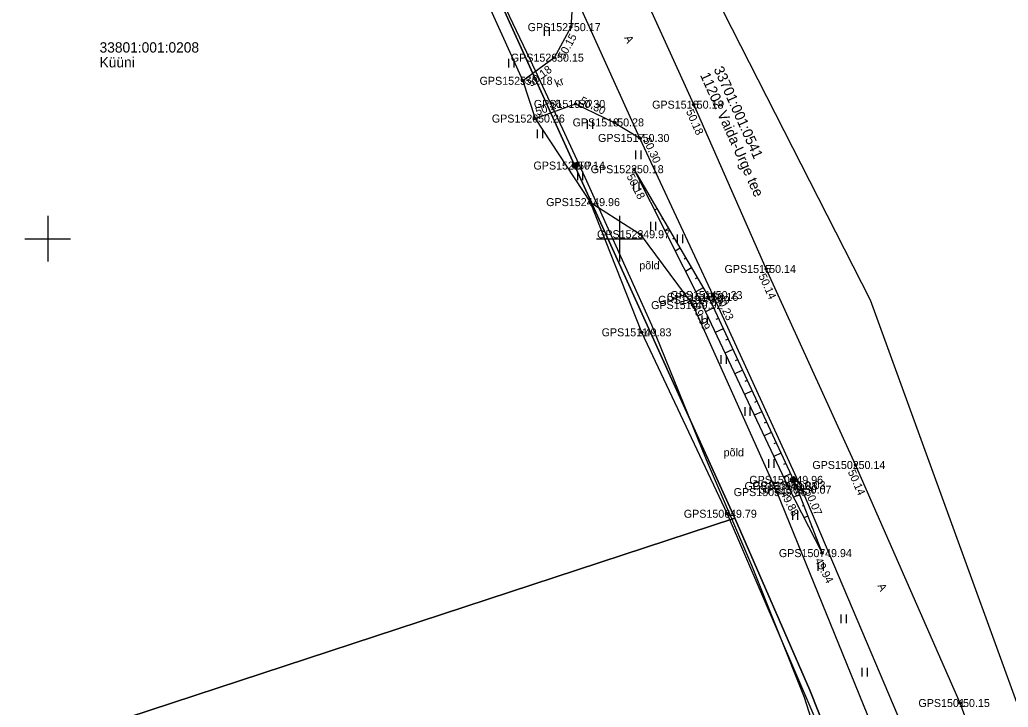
# Model space of a CAD drawing. Extents: x 551623 to 559850, y 6561220 to 6567135.
# Drawn here: x 555097.6 to 555184, y 6565359 to 6565419.1 of the extents above; entities that cross this region are included whole.
import ezdxf

# ---------------------------------------------------------------- set-up
doc = ezdxf.new("R2010")
doc.units = 0
for name, color, linetype in [('HALJASTUS', 7, 'Continuous'), ('KORGUS-EH2000', 7, 'Continuous'), ('KPKAABEL', 7, 'Continuous'), ('MOOTKORG-EH2000', 7, 'Continuous'), ('MOOTMPUNKT', 7, 'Continuous'), ('MOOTNR', 7, 'Continuous'), ('MOOTPIIR', 7, 'Continuous'), ('PIIR', 7, 'Continuous'), ('POST', 7, 'Continuous'), ('RELJEEF', 7, 'Continuous'), ('TEE', 7, 'Continuous'), ('VORK', 7, 'Continuous')]:
    doc.layers.add(name, color=color, linetype=linetype)

msp = doc.modelspace()

# ---------------------------------------------------------------- linework, layer by layer
at = {"layer": 'HALJASTUS'}
for p, q in [((555143.4, 6565418.501), (555143.4, 6565417.739)), ((555143.855, 6565418.501), (555143.855, 6565417.739)), ((555140.305, 6565415.73), (555140.305, 6565414.969)), ((555140.76, 6565415.73), (555140.76, 6565414.969)), ((555147.172, 6565410.363), (555147.172, 6565409.602)), ((555147.627, 6565410.363), (555147.627, 6565409.602)), ((555142.801, 6565409.556), (555142.801, 6565408.795)), ((555143.256, 6565409.556), (555143.256, 6565408.795)), ((555151.41, 6565407.71), (555151.41, 6565406.949)), ((555151.865, 6565407.71), (555151.865, 6565406.949)), ((555146.315, 6565405.877), (555146.315, 6565405.116)), ((555146.77, 6565405.877), (555146.77, 6565405.116)), ((555151.235, 6565404.982), (555151.235, 6565404.221)), ((555151.69, 6565404.982), (555151.69, 6565404.221)), ((555152.696, 6565401.486), (555152.696, 6565400.724)), ((555153.151, 6565401.486), (555153.151, 6565400.724)), ((555155.056, 6565400.377), (555155.056, 6565399.616)), ((555155.511, 6565400.377), (555155.511, 6565399.616)), ((555157.198, 6565393.27), (555157.198, 6565392.509)), ((555157.654, 6565393.27), (555157.654, 6565392.509)), ((555158.86, 6565389.801), (555158.86, 6565389.04)), ((555159.315, 6565389.801), (555159.315, 6565389.04)), ((555160.947, 6565385.258), (555160.947, 6565384.497)), ((555161.402, 6565385.258), (555161.402, 6565384.497)), ((555163.034, 6565380.714), (555163.034, 6565379.953)), ((555163.489, 6565380.714), (555163.489, 6565379.953)), ((555165.121, 6565376.171), (555165.121, 6565375.41)), ((555165.576, 6565376.171), (555165.576, 6565375.41)), ((555167.351, 6565371.697), (555167.351, 6565370.935)), ((555167.806, 6565371.697), (555167.806, 6565370.935)), ((555169.366, 6565367.127), (555169.366, 6565366.366)), ((555169.821, 6565367.127), (555169.821, 6565366.366)), ((555171.205, 6565362.477), (555171.205, 6565361.716)), ((555171.66, 6565362.477), (555171.66, 6565361.716))]:
    msp.add_line(p, q, dxfattribs=at)
msp.add_lwpolyline([(555147.437, 6565403.198), (555151.813, 6565400.39), (555156.402, 6565394.192), (555163.761, 6565377.834), (555172.39, 6565356.6), (555175.608, 6565345.88), (555178.387, 6565334.156), (555180.524, 6565321.581), (555178.521, 6565317.128)], dxfattribs=at)
at = {"layer": 'KORGUS-EH2000'}
for centre in [(555144.275, 6565415.829), (555141.543, 6565413.808), (555146.15, 6565411.784), (555156.491, 6565411.721), (555142.614, 6565410.505), (555151.76, 6565408.809), (555151.259, 6565406.076), (555147.437, 6565403.198), (555151.813, 6565400.39), (555162.823, 6565397.349), (555158.151, 6565395.066), (555157.023, 6565394.648), (555151.936, 6565391.81), (555170.643, 6565380.205), (555164.713, 6565378.366), (555165.412, 6565378.436), (555165.93, 6565378.047), (555159.402, 6565375.941), (555167.716, 6565372.497), (555179.78, 6565359.387)]:
    msp.add_circle(centre, 0.1, dxfattribs=at)
at = {"layer": 'KPKAABEL'}
msp.add_lwpolyline([(555062.108, 6565572.667), (555068.248, 6565560.982), (555073.771, 6565549.852), (555080.106, 6565537.978), (555085.958, 6565527.605), (555092.403, 6565515.607), (555098.402, 6565504.536), (555104.641, 6565492.438), (555110.839, 6565480.82), (555116.697, 6565469.072), (555121.821, 6565458.116), (555126.894, 6565446.731), (555132.737, 6565435.388), (555136.366, 6565427.872), (555142.195, 6565415.637), (555145.001, 6565409.613), (555146.957, 6565405.365), (555152.799, 6565392.474), (555157.576, 6565380.671), (555161.529, 6565371.444), (555166.139, 6565359.889), (555169.783, 6565348.422)], dxfattribs=at)
at = {"layer": 'MOOTMPUNKT'}
for centre in [(555145.745, 6565418.501), (555144.275, 6565415.829), (555141.543, 6565413.808), (555146.15, 6565411.784), (555156.491, 6565411.721), (555142.614, 6565410.505), (555149.538, 6565410.169), (555151.76, 6565408.809), (555146.117, 6565406.394), (555151.259, 6565406.076), (555147.437, 6565403.198), (555151.813, 6565400.39), (555162.823, 6565397.349), (555158.151, 6565395.066), (555156.402, 6565394.192), (555157.023, 6565394.648), (555157.779, 6565394.908), (555151.936, 6565391.81), (555170.643, 6565380.205), (555165.2, 6565378.903), (555163.761, 6565377.834), (555164.713, 6565378.366), (555165.412, 6565378.436), (555165.93, 6565378.047), (555159.402, 6565375.941), (555167.716, 6565372.497), (555179.78, 6565359.387)]:
    msp.add_circle(centre, 0.1, dxfattribs=at)
at = {"layer": 'MOOTPIIR'}
for points in [[(555183.958, 6565348.1), (555179.78, 6565359.387), (555170.643, 6565380.205), (555162.823, 6565397.349), (555156.491, 6565411.721), (555150.933, 6565424.006), (555146.697, 6565433.416), (555136.695, 6565455.531), (555128.269, 6565473.276), (555117.193, 6565494.735), (555104.647, 6565516.948), (555091.543, 6565539.738), (555085.215, 6565551.468), (555079.648, 6565563.241), (555074.002, 6565577.71)], [(555063.202, 6565573.546), (555069.448, 6565559.262), (555074.798, 6565546.065), (555081.393, 6565533.703), (555093.795, 6565510.023), (555105.564, 6565489.366), (555116.679, 6565467.661), (555125.053, 6565451.606), (555137.448, 6565422.907), (555141.543, 6565413.808), (555142.614, 6565410.505), (555147.437, 6565403.198), (555151.936, 6565391.81), (555159.402, 6565375.941), (555168.348, 6565355.185)]]:
    msp.add_lwpolyline(points, dxfattribs=at)
at = {"layer": 'PIIR'}
for points in [[(555524.79, 6565820.16), (555464.46, 6565652.92), (555447.97, 6565611.96), (555353.12, 6565523.87), (555343.14, 6565512.46), (555302.6, 6565539.71), (555242.37, 6565583.94), (555179.42, 6565586.32), (555138.98, 6565580.6), (555121.18, 6565602.26), (555116.17, 6565610.5), (555109.96, 6565624.83), (555093.56, 6565628.47), (555079.04, 6565618.4), (555074.13, 6565607.82), (555075.34, 6565593.24), (555091.74, 6565551.94), (555171.91, 6565394.64), (555191.35, 6565341.19)], [(554759.9, 6565289.12), (554708.97, 6565534.83), (554708.61, 6565545.48), (554711.27, 6565557.85), (554755.81, 6565778.04), (554759.53, 6565776.27), (554842.52, 6565736.67), (555030.24, 6565648.23), (555043.11, 6565640.11), (555053.62, 6565632.14), (555056.61, 6565622.91), (555057.22, 6565600.73), (555060.42, 6565583.26), (555065.78, 6565566.7), (555076.76, 6565542.38), (555113.82, 6565475.68), (554946.63, 6565420.78), (554981.01, 6565316.76), (555160.07, 6565375.54), (555166.64, 6565360.5), (555172.72, 6565345.23)], [(555172.72, 6565345.23), (555166.64, 6565360.5), (555160.07, 6565375.54), (555144.16, 6565410.6), (555124.27, 6565454.45), (555113.82, 6565475.68), (555076.76, 6565542.38), (555065.78, 6565566.7), (555060.42, 6565583.26), (555057.22, 6565600.73), (555056.61, 6565622.91), (555063.43, 6565647.29), (555114.24, 6565634), (555129.77, 6565611.2), (555130.73, 6565621.32), (555138.66, 6565615.26), (555160.12, 6565598.86), (555193.24, 6565604.68)]]:
    msp.add_lwpolyline(points, dxfattribs=at)
msp.add_lwpolyline([(554981.01, 6565316.76), (554946.63, 6565420.78), (555113.82, 6565475.68), (555124.27, 6565454.45), (555144.16, 6565410.6), (555160.07, 6565375.54)], close=True, dxfattribs=at)
at = {"layer": 'POST'}
msp.add_line((555165.022, 6565378.727), (555165.376, 6565379.08), dxfattribs=at)
for centre, radius in [((555146.117, 6565406.394), 0.25), ((555146.117, 6565406.394), 0.225), ((555146.117, 6565406.394), 0.2), ((555146.117, 6565406.394), 0.175), ((555146.117, 6565406.394), 0.15), ((555146.117, 6565406.394), 0.125), ((555146.117, 6565406.394), 0.1), ((555146.117, 6565406.394), 0.075), ((555146.117, 6565406.394), 0.05), ((555146.117, 6565406.394), 0.025), ((555165.2, 6565378.903), 0.25)]:
    msp.add_circle(centre, radius, dxfattribs=at)
for radius, start, end in [(0.225, 224.85406, 45.03563), (0.2, 224.84272, 45.04698), (0.175, 224.82813, 45.06157), (0.15, 224.80867, 45.08103), (0.125, 224.78144, 45.10826), (0.1, 224.74058, 45.14911), (0.075, 224.67249, 45.2172), (0.05, 224.53632, 45.35338), (0.025, 224.12776, 45.76193)]:
    msp.add_arc((555165.2, 6565378.903), radius, start, end, dxfattribs=at)
at = {"layer": 'RELJEEF'}
for p, q in [((555151.764, 6565405.213), (555151.748, 6565405.203)), ((555152.268, 6565404.349), (555152.162, 6565404.287)), ((555152.772, 6565403.485), (555152.724, 6565403.458)), ((555153.276, 6565402.622), (555153.064, 6565402.498)), ((555153.78, 6565401.758), (555153.701, 6565401.712)), ((555154.284, 6565400.895), (555153.966, 6565400.709)), ((555154.788, 6565400.031), (555154.677, 6565399.966)), ((555155.292, 6565399.167), (555154.868, 6565398.92)), ((555155.796, 6565398.304), (555155.653, 6565398.22)), ((555156.301, 6565397.44), (555155.771, 6565397.131)), ((555156.805, 6565396.576), (555156.63, 6565396.474)), ((555157.309, 6565395.713), (555156.673, 6565395.341)), ((555157.807, 6565394.846), (555157.591, 6565394.746)), ((555158.228, 6565393.939), (555157.514, 6565393.608)), ((555158.648, 6565393.031), (555158.436, 6565392.933)), ((555159.069, 6565392.124), (555158.368, 6565391.799)), ((555159.489, 6565391.217), (555159.281, 6565391.12)), ((555159.91, 6565390.31), (555159.222, 6565389.991)), ((555160.33, 6565389.402), (555160.126, 6565389.308)), ((555160.751, 6565388.495), (555160.076, 6565388.183)), ((555161.171, 6565387.588), (555160.971, 6565387.495)), ((555161.592, 6565386.68), (555160.931, 6565386.374)), ((555162.012, 6565385.773), (555161.816, 6565385.682)), ((555162.432, 6565384.866), (555161.785, 6565384.566)), ((555162.853, 6565383.958), (555162.661, 6565383.869)), ((555163.273, 6565383.051), (555162.639, 6565382.757)), ((555163.694, 6565382.144), (555163.505, 6565382.057)), ((555164.114, 6565381.237), (555163.493, 6565380.949)), ((555164.535, 6565380.329), (555164.35, 6565380.244)), ((555164.955, 6565379.422), (555164.347, 6565379.14)), ((555165.376, 6565378.515), (555165.197, 6565378.432)), ((555165.742, 6565377.584), (555165.217, 6565377.381)), ((555166.104, 6565376.652), (555165.975, 6565376.602)), ((555166.466, 6565375.72), (555166.133, 6565375.591)), ((555166.827, 6565374.787), (555166.756, 6565374.76)), ((555167.189, 6565373.855), (555167.049, 6565373.801)), ((555167.55, 6565372.923), (555167.537, 6565372.918))]:
    msp.add_line(p, q, dxfattribs=at)
for points in [[(555151.259, 6565406.076), (555157.779, 6565394.908), (555165.412, 6565378.436), (555167.716, 6565372.497)], [(555151.259, 6565406.076), (555157.023, 6565394.648), (555164.713, 6565378.366), (555167.716, 6565372.497)]]:
    msp.add_lwpolyline(points, dxfattribs=at)
at = {"layer": 'TEE'}
for points in [[(555183.958, 6565348.1), (555179.78, 6565359.387), (555170.643, 6565380.205), (555162.823, 6565397.349), (555156.491, 6565411.721), (555150.933, 6565424.006), (555146.697, 6565433.416), (555136.695, 6565455.531), (555128.269, 6565473.276), (555117.193, 6565494.735), (555104.647, 6565516.948), (555091.543, 6565539.738), (555085.215, 6565551.468), (555079.648, 6565563.241), (555074.002, 6565577.71), (555071.343, 6565586.858), (555069.389, 6565597.535), (555068.634, 6565604.431)], [(555063.038, 6565604.031), (555063.892, 6565596.591), (555066.154, 6565585.551), (555068.837, 6565576.18), (555074.683, 6565560.943), (555080.389, 6565548.865), (555086.718, 6565537.194), (555099.86, 6565513.945), (555112.002, 6565492.197), (555123.272, 6565470.871), (555131.266, 6565453.894), (555141.635, 6565431.431), (555145.957, 6565421.634), (555151.76, 6565408.809), (555158.151, 6565395.066), (555165.93, 6565378.047), (555174.733, 6565357.312)], [(555145.957, 6565421.634), (555145.745, 6565418.501), (555144.275, 6565415.829), (555141.543, 6565413.808)], [(555142.614, 6565410.505), (555146.15, 6565411.784), (555149.538, 6565410.169), (555151.76, 6565408.809)]]:
    msp.add_lwpolyline(points, dxfattribs=at)
at = {"layer": 'VORK'}
for p, q in [((555100, 6565402), (555100, 6565398)), ((555150, 6565402), (555150, 6565398)), ((555098, 6565400), (555102, 6565400)), ((555148, 6565400), (555152, 6565400))]:
    msp.add_line(p, q, dxfattribs=at)

# ---------------------------------------------------------------- texts
at = {"layer": 'HALJASTUS'}
for p in [(555151.734, 6565397.316), (555159.107, 6565380.958)]:
    msp.add_text('põld', height=0.7, rotation=359.95437, dxfattribs=at).set_placement(p)
at = {"layer": 'KORGUS-EH2000'}
for s, rotation, p in [(' 50.15', 61.18954, (555145.042, 6565415.407)), (' 50.18', 36.49057, (555142.063, 6565413.104)), (' 50.30', 334.5207, (555146.225, 6565411.942)), (' 50.26', 19.87584, (555142.554, 6565410.67)), (' 50.18', 293.77694, (555155.691, 6565411.368)), (' 50.30', 294.93897, (555151.919, 6565408.883)), (' 50.18', 296.76164, (555150.478, 6565405.682)), (' 50.14', 294.51909, (555162.027, 6565396.986)), (' 50.23', 294.5645, (555158.31, 6565395.139)), (' 49.99', 295.28169, (555156.232, 6565394.274)), (' 50.14', 293.69457, (555169.842, 6565379.853)), (' 50.07', 293.00428, (555166.091, 6565378.115)), (' 49.88', 297.0964, (555163.934, 6565377.967)), (' 49.94', 297.0964, (555166.937, 6565372.099))]:
    msp.add_text(s, height=0.7, rotation=rotation, dxfattribs=at).set_placement(p)
for s, p in [(' 49.96', (555147.437, 6565402.848)), (' 49.97', (555151.813, 6565400.04)), (' 49.83', (555151.936, 6565391.46)), (' 49.79', (555159.402, 6565375.591))]:
    msp.add_text(s, height=0.7, dxfattribs=at).set_placement(p)
at = {"layer": 'MOOTKORG-EH2000'}
for s, p in [(' 50.17', (555145.745, 6565418.151)), (' 50.15', (555144.275, 6565415.479)), (' 50.18', (555141.543, 6565413.458)), (' 50.30', (555146.15, 6565411.434)), (' 50.18', (555156.491, 6565411.371)), (' 50.26', (555142.614, 6565410.155)), (' 50.28', (555149.538, 6565409.819)), (' 50.30', (555151.76, 6565408.459)), (' 50.14', (555146.117, 6565406.044)), (' 50.18', (555151.259, 6565405.726)), (' 49.96', (555147.437, 6565402.848)), (' 49.97', (555151.813, 6565400.04)), (' 50.14', (555162.823, 6565396.999)), (' 50.16', (555157.779, 6565394.558)), (' 50.23', (555158.151, 6565394.716)), (' 49.92', (555156.402, 6565393.842)), (' 49.99', (555157.023, 6565394.298)), (' 49.83', (555151.936, 6565391.46)), (' 50.14', (555170.643, 6565379.855)), (' 49.88', (555164.713, 6565378.016)), (' 49.96', (555165.2, 6565378.553)), (' 50.03', (555165.412, 6565378.086)), (' 49.86', (555163.761, 6565377.484)), (' 50.07', (555165.93, 6565377.697)), (' 49.79', (555159.402, 6565375.591)), (' 49.94', (555167.716, 6565372.147)), (' 50.15', (555179.78, 6565359.036))]:
    msp.add_text(s, height=0.7, dxfattribs=at).set_placement(p)
at = {"layer": 'MOOTNR'}
for s, p in [('GPS1527 ', (555141.965, 6565418.151)), ('GPS1526 ', (555140.495, 6565415.479)), ('GPS1525 ', (555137.763, 6565413.458)), ('GPS1519 ', (555142.51, 6565411.434)), ('GPS1516 ', (555152.852, 6565411.371)), ('GPS1520 ', (555138.834, 6565410.155)), ('GPS1518 ', (555145.898, 6565409.819)), ('GPS1517 ', (555148.121, 6565408.459)), ('GPS1521 ', (555142.477, 6565406.044)), ('GPS1522 ', (555147.48, 6565405.726)), ('GPS1524 ', (555143.587, 6565402.848)), ('GPS1523 ', (555148.033, 6565400.04)), ('GPS1515 ', (555159.184, 6565396.999)), ('GPS1513 ', (555154.139, 6565394.558)), ('GPS1514 ', (555154.441, 6565394.716)), ('GPS1510 ', (555152.763, 6565393.842)), ('GPS1512 ', (555153.383, 6565394.298)), ('GPS1511 ', (555148.436, 6565391.46)), ('GPS1502 ', (555166.864, 6565379.855)), ('GPS1509 ', (555160.933, 6565378.016)), ('GPS1504 ', (555161.35, 6565378.553)), ('GPS1508 ', (555161.632, 6565378.086)), ('GPS1505 ', (555159.981, 6565377.484)), ('GPS1503 ', (555162.151, 6565377.697)), ('GPS1506 ', (555155.622, 6565375.591)), ('GPS1507 ', (555163.936, 6565372.147)), ('GPS1501 ', (555176.14, 6565359.036))]:
    msp.add_text(s, height=0.7, dxfattribs=at).set_placement(p)
at = {"layer": 'PIIR'}
for s, p in [('33801:001:0208', (555104.531, 6565416.279)), ('Küüni', (555104.531, 6565414.979))]:
    msp.add_text(s, height=0.9, dxfattribs=at).set_placement(p)
for s, p in [('33701:001:0541', (555158.212, 6565414.837)), ('11202 Vaida-Urge tee', (555157.026, 6565414.306))]:
    msp.add_text(s, height=0.9, rotation=294.0992, dxfattribs=at).set_placement(p)
at = {"layer": 'POST'}
msp.add_text(' TP', height=0.7, dxfattribs=at).set_placement((555146.117, 6565406.044))
at = {"layer": 'TEE'}
for s, rotation, p in [('A', 295.47788, (555150.395, 6565417.576)), ('kr', 23.68796, (555144.514, 6565413.221)), ('A', 295.58141, (555172.545, 6565369.65))]:
    msp.add_text(s, height=0.7, rotation=rotation, dxfattribs=at).set_placement(p)

doc.saveas('drawing.dxf')
